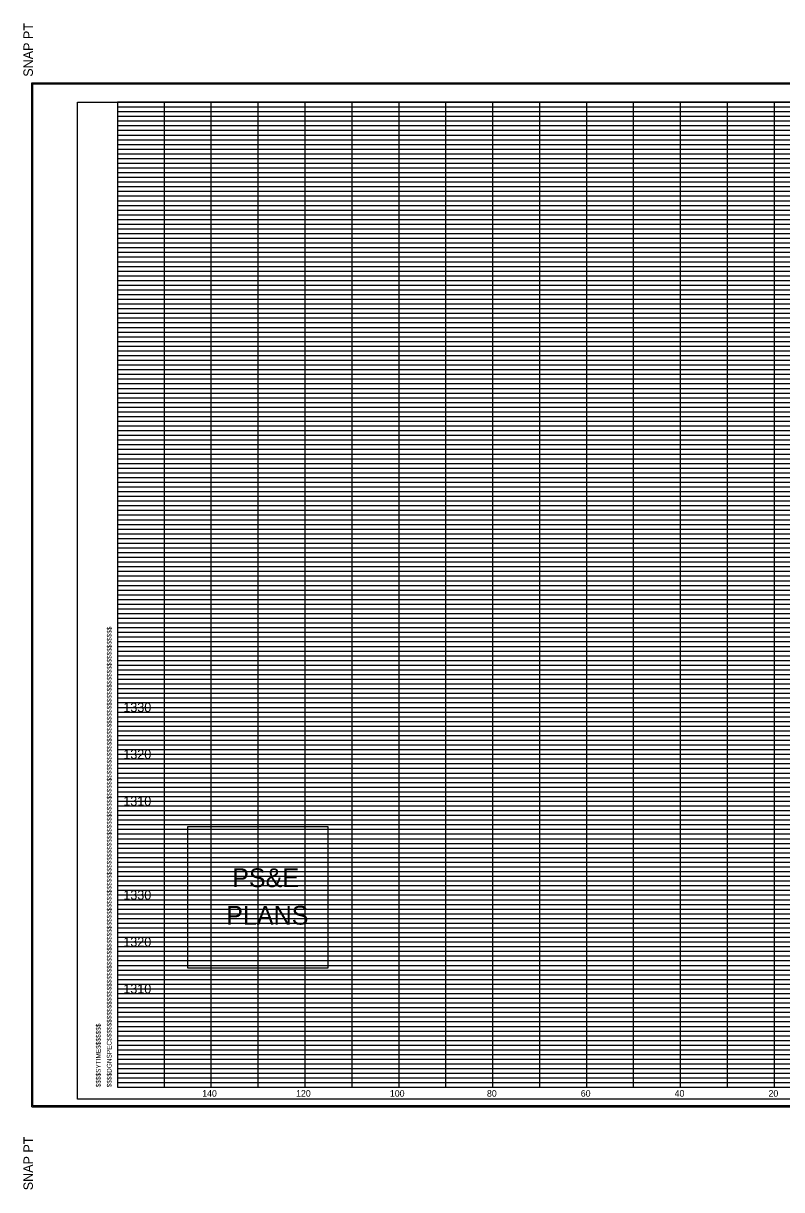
# Model space of a CAD drawing. Extents: x 980 to 1324, y 978 to 1227.
# Drawn here: x 979.9 to 1141.5, y 978.2 to 1226.8 of the extents above; entities that cross this region are included whole.
import ezdxf

# ---------------------------------------------------------------- set-up
doc = ezdxf.new("R2010")
doc.units = 0
for name, color, linetype in [('DESIGN - SHEET - Corner Text', 7, 'Continuous'), ('DESIGN - SHEET - Light Grid', 7, 'Continuous'), ('DESIGN - SHEET - Linework', 7, 'Continuous'), ('DESIGN - SHEET - Plot Shape', 7, 'Continuous'), ('DESIGN - TYPICAL - Finished Grade and Subgrade', 7, 'Continuous')]:
    doc.layers.add(name, color=color, linetype=linetype)

# ---------------------------------------------------------------- blocks, each defined once
blk = doc.blocks.new('XSTSHT')
at = {"layer": 'DESIGN - SHEET - Light Grid'}
for p, q in [((0, 20.9), (8, 20.9)), ((8, 20.9), (16, 20.9)), ((0, 20.8), (8, 20.8)), ((0, 20.7), (8, 20.7)), ((8, 20.8), (16, 20.8)), ((8, 20.7), (16, 20.7)), ((0, 20.6), (8, 20.6)), ((0, 20.5), (8, 20.5)), ((0, 20.4), (8, 20.4)), ((8, 20.6), (16, 20.6)), ((8, 20.5), (16, 20.5)), ((8, 20.4), (16, 20.4)), ((0, 20.3), (8, 20.3)), ((0, 20.2), (8, 20.2)), ((8, 20.3), (16, 20.3)), ((8, 20.2), (16, 20.2)), ((0, 20.1), (8, 20.1)), ((0, 19.9), (8, 19.9)), ((8, 20.1), (16, 20.1)), ((8, 19.9), (16, 19.9)), ((0, 19.8), (8, 19.8)), ((0, 19.7), (8, 19.7)), ((8, 19.8), (16, 19.8)), ((8, 19.7), (16, 19.7)), ((0, 19.6), (8, 19.6)), ((0, 19.5), (8, 19.5)), ((0, 19.4), (8, 19.4)), ((8, 19.6), (16, 19.6)), ((8, 19.5), (16, 19.5)), ((8, 19.4), (16, 19.4)), ((0, 19.3), (8, 19.3)), ((0, 19.2), (8, 19.2)), ((8, 19.3), (16, 19.3)), ((8, 19.2), (16, 19.2)), ((0, 19.1), (8, 19.1)), ((0, 18.9), (8, 18.9)), ((8, 19.1), (16, 19.1)), ((8, 18.9), (16, 18.9)), ((0, 18.8), (8, 18.8)), ((0, 18.7), (8, 18.7)), ((8, 18.8), (16, 18.8)), ((8, 18.7), (16, 18.7)), ((0, 18.6), (8, 18.6)), ((0, 18.5), (8, 18.5)), ((0, 18.4), (8, 18.4)), ((8, 18.6), (16, 18.6)), ((8, 18.5), (16, 18.5)), ((8, 18.4), (16, 18.4)), ((0, 18.3), (8, 18.3)), ((0, 18.2), (8, 18.2)), ((8, 18.3), (16, 18.3)), ((8, 18.2), (16, 18.2)), ((0, 18.1), (8, 18.1)), ((8, 18.1), (16, 18.1)), ((0, 17.9), (8, 17.9)), ((0, 17.8), (8, 17.8)), ((0, 17.7), (8, 17.7)), ((8, 17.9), (16, 17.9)), ((8, 17.8), (16, 17.8)), ((8, 17.7), (16, 17.7)), ((0, 17.6), (8, 17.6)), ((0, 17.5), (8, 17.5)), ((8, 17.6), (16, 17.6)), ((8, 17.5), (16, 17.5)), ((0, 17.4), (8, 17.4)), ((0, 17.3), (8, 17.3)), ((0, 17.2), (8, 17.2)), ((8, 17.4), (16, 17.4)), ((8, 17.3), (16, 17.3)), ((8, 17.2), (16, 17.2)), ((0, 17.1), (8, 17.1)), ((8, 17.1), (16, 17.1)), ((0, 16.9), (8, 16.9)), ((0, 16.8), (8, 16.8)), ((0, 16.7), (8, 16.7)), ((8, 16.9), (16, 16.9)), ((8, 16.8), (16, 16.8)), ((8, 16.7), (16, 16.7)), ((0, 16.6), (8, 16.6)), ((0, 16.5), (8, 16.5)), ((8, 16.6), (16, 16.6)), ((8, 16.5), (16, 16.5)), ((0, 16.4), (8, 16.4)), ((0, 16.3), (8, 16.3)), ((0, 16.2), (8, 16.2)), ((8, 16.4), (16, 16.4)), ((8, 16.3), (16, 16.3)), ((8, 16.2), (16, 16.2)), ((0, 16.1), (8, 16.1)), ((8, 16.1), (16, 16.1)), ((0, 15.9), (8, 15.9)), ((0, 15.8), (8, 15.8)), ((0, 15.7), (8, 15.7)), ((8, 15.9), (16, 15.9)), ((8, 15.8), (16, 15.8)), ((8, 15.7), (16, 15.7)), ((0, 15.6), (8, 15.6)), ((0, 15.5), (8, 15.5)), ((8, 15.6), (16, 15.6)), ((8, 15.5), (16, 15.5)), ((0, 15.4), (8, 15.4)), ((0, 15.3), (8, 15.3)), ((0, 15.2), (8, 15.2)), ((8, 15.4), (16, 15.4)), ((8, 15.3), (16, 15.3)), ((8, 15.2), (16, 15.2)), ((0, 15.1), (8, 15.1)), ((8, 15.1), (16, 15.1)), ((0, 14.9), (8, 14.9)), ((0, 14.8), (8, 14.8)), ((0, 14.7), (8, 14.7)), ((8, 14.9), (16, 14.9)), ((8, 14.8), (16, 14.8)), ((8, 14.7), (16, 14.7)), ((0, 14.6), (8, 14.6)), ((0, 14.5), (8, 14.5)), ((8, 14.6), (16, 14.6)), ((8, 14.5), (16, 14.5)), ((0, 14.4), (8, 14.4)), ((0, 14.3), (8, 14.3)), ((0, 14.2), (8, 14.2)), ((8, 14.4), (16, 14.4)), ((8, 14.3), (16, 14.3)), ((8, 14.2), (16, 14.2)), ((0, 14.1), (8, 14.1)), ((8, 14.1), (16, 14.1)), ((0, 13.9), (8, 13.9)), ((0, 13.8), (8, 13.8)), ((0, 13.7), (8, 13.7)), ((8, 13.9), (16, 13.9)), ((8, 13.8), (16, 13.8)), ((8, 13.7), (16, 13.7)), ((0, 13.6), (8, 13.6)), ((0, 13.5), (8, 13.5)), ((8, 13.6), (16, 13.6)), ((8, 13.5), (16, 13.5)), ((0, 13.4), (8, 13.4)), ((0, 13.3), (8, 13.3)), ((0, 13.2), (8, 13.2)), ((8, 13.4), (16, 13.4)), ((8, 13.3), (16, 13.3)), ((8, 13.2), (16, 13.2)), ((0, 13.1), (8, 13.1)), ((8, 13.1), (16, 13.1)), ((0, 12.9), (8, 12.9)), ((0, 12.8), (8, 12.8)), ((0, 12.7), (8, 12.7)), ((8, 12.9), (16, 12.9)), ((8, 12.8), (16, 12.8)), ((8, 12.7), (16, 12.7)), ((0, 12.6), (8, 12.6)), ((0, 12.5), (8, 12.5)), ((8, 12.6), (16, 12.6)), ((8, 12.5), (16, 12.5)), ((0, 12.4), (8, 12.4)), ((0, 12.3), (8, 12.3)), ((0, 12.2), (8, 12.2)), ((8, 12.4), (16, 12.4)), ((8, 12.3), (16, 12.3)), ((8, 12.2), (16, 12.2)), ((0, 12.1), (8, 12.1)), ((8, 12.1), (16, 12.1)), ((0, 11.9), (8, 11.9)), ((0, 11.8), (8, 11.8)), ((0, 11.7), (8, 11.7)), ((8, 11.9), (16, 11.9)), ((8, 11.8), (16, 11.8)), ((8, 11.7), (16, 11.7)), ((0, 11.6), (8, 11.6)), ((0, 11.5), (8, 11.5)), ((8, 11.6), (16, 11.6)), ((8, 11.5), (16, 11.5)), ((0, 11.4), (8, 11.4)), ((0, 11.3), (8, 11.3)), ((0, 11.2), (8, 11.2)), ((8, 11.4), (16, 11.4)), ((8, 11.3), (16, 11.3)), ((8, 11.2), (16, 11.2)), ((0, 11.1), (8, 11.1)), ((8, 11.1), (16, 11.1)), ((0, 10.9), (8, 10.9)), ((0, 10.8), (8, 10.8)), ((0, 10.7), (8, 10.7)), ((8, 10.9), (16, 10.9)), ((8, 10.8), (16, 10.8)), ((8, 10.7), (16, 10.7)), ((0, 10.6), (8, 10.6)), ((0, 10.5), (8, 10.5)), ((8, 10.6), (16, 10.6)), ((8, 10.5), (16, 10.5)), ((0, 10.4), (8, 10.4)), ((0, 10.3), (8, 10.3)), ((0, 10.2), (8, 10.2)), ((8, 10.4), (16, 10.4)), ((8, 10.3), (16, 10.3)), ((8, 10.2), (16, 10.2)), ((0, 10.1), (8, 10.1)), ((8, 10.1), (16, 10.1)), ((0, 9.9), (8, 9.9)), ((0, 9.8), (8, 9.8)), ((0, 9.7), (8, 9.7)), ((8, 9.9), (16, 9.9)), ((8, 9.8), (16, 9.8)), ((8, 9.7), (16, 9.7)), ((0, 9.6), (8, 9.6)), ((0, 9.5), (8, 9.5)), ((8, 9.6), (16, 9.6)), ((8, 9.5), (16, 9.5)), ((0, 9.4), (8, 9.4)), ((0, 9.3), (8, 9.3)), ((0, 9.2), (8, 9.2)), ((8, 9.4), (16, 9.4)), ((8, 9.3), (16, 9.3)), ((8, 9.2), (16, 9.2)), ((0, 9.1), (8, 9.1)), ((8, 9.1), (16, 9.1)), ((0, 8.9), (8, 8.9)), ((0, 8.8), (8, 8.8)), ((8, 8.9), (16, 8.9)), ((8, 8.8), (16, 8.8)), ((0, 8.7), (8, 8.7)), ((0, 8.6), (8, 8.6)), ((0, 8.5), (8, 8.5)), ((8, 8.7), (16, 8.7)), ((8, 8.6), (16, 8.6)), ((8, 8.5), (16, 8.5)), ((0, 8.4), (8, 8.4)), ((0, 8.3), (8, 8.3)), ((8, 8.4), (16, 8.4)), ((8, 8.3), (16, 8.3)), ((0, 8.2), (8, 8.2)), ((0, 8.1), (8, 8.1)), ((8, 8.2), (16, 8.2)), ((8, 8.1), (16, 8.1)), ((0, 7.9), (8, 7.9)), ((0, 7.8), (8, 7.8)), ((8, 7.9), (16, 7.9)), ((8, 7.8), (16, 7.8)), ((0, 7.7), (8, 7.7)), ((0, 7.6), (8, 7.6)), ((0, 7.5), (8, 7.5)), ((8, 7.7), (16, 7.7)), ((8, 7.6), (16, 7.6)), ((8, 7.5), (16, 7.5)), ((0, 7.4), (8, 7.4)), ((0, 7.3), (8, 7.3)), ((8, 7.4), (16, 7.4)), ((8, 7.3), (16, 7.3)), ((0, 7.2), (8, 7.2)), ((0, 7.1), (8, 7.1)), ((8, 7.2), (16, 7.2)), ((8, 7.1), (16, 7.1)), ((0, 6.9), (8, 6.9)), ((0, 6.8), (8, 6.8)), ((8, 6.9), (16, 6.9)), ((8, 6.8), (16, 6.8)), ((0, 6.7), (8, 6.7)), ((0, 6.6), (8, 6.6)), ((0, 6.5), (8, 6.5)), ((8, 6.7), (16, 6.7)), ((8, 6.6), (16, 6.6)), ((8, 6.5), (16, 6.5)), ((0, 6.4), (8, 6.4)), ((0, 6.3), (8, 6.3)), ((8, 6.4), (16, 6.4)), ((8, 6.3), (16, 6.3)), ((0, 6.2), (8, 6.2)), ((0, 6.1), (8, 6.1)), ((8, 6.2), (16, 6.2)), ((8, 6.1), (16, 6.1)), ((0, 5.9), (8, 5.9)), ((0, 5.8), (8, 5.8)), ((8, 5.9), (16, 5.9)), ((8, 5.8), (16, 5.8)), ((0, 5.7), (8, 5.7)), ((0, 5.6), (8, 5.6)), ((0, 5.5), (8, 5.5)), ((8, 5.7), (16, 5.7)), ((8, 5.6), (16, 5.6)), ((8, 5.5), (16, 5.5)), ((0, 5.4), (8, 5.4)), ((0, 5.3), (8, 5.3)), ((8, 5.4), (16, 5.4)), ((8, 5.3), (16, 5.3)), ((0, 5.2), (8, 5.2)), ((0, 5.1), (8, 5.1)), ((8, 5.2), (16, 5.2)), ((8, 5.1), (16, 5.1)), ((0, 4.9), (8, 4.9)), ((0, 4.8), (8, 4.8)), ((8, 4.9), (16, 4.9)), ((8, 4.8), (16, 4.8)), ((0, 4.7), (8, 4.7)), ((0, 4.6), (8, 4.6)), ((0, 4.5), (8, 4.5)), ((8, 4.7), (16, 4.7)), ((8, 4.6), (16, 4.6)), ((8, 4.5), (16, 4.5)), ((0, 4.4), (8, 4.4)), ((0, 4.3), (8, 4.3)), ((8, 4.4), (16, 4.4)), ((8, 4.3), (16, 4.3)), ((0, 4.2), (8, 4.2)), ((0, 4.1), (8, 4.1)), ((8, 4.2), (16, 4.2)), ((8, 4.1), (16, 4.1)), ((0, 3.9), (8, 3.9)), ((0, 3.8), (8, 3.8)), ((8, 3.9), (16, 3.9)), ((8, 3.8), (16, 3.8)), ((0, 3.7), (8, 3.7)), ((0, 3.6), (8, 3.6)), ((0, 3.5), (8, 3.5)), ((8, 3.7), (16, 3.7)), ((8, 3.6), (16, 3.6)), ((8, 3.5), (16, 3.5)), ((0, 3.4), (8, 3.4)), ((0, 3.3), (8, 3.3)), ((8, 3.4), (16, 3.4)), ((8, 3.3), (16, 3.3)), ((0, 3.2), (8, 3.2)), ((0, 3.1), (8, 3.1)), ((8, 3.2), (16, 3.2)), ((8, 3.1), (16, 3.1)), ((0, 2.9), (8, 2.9)), ((0, 2.8), (8, 2.8)), ((8, 2.9), (16, 2.9)), ((8, 2.8), (16, 2.8)), ((0, 2.7), (8, 2.7)), ((0, 2.6), (8, 2.6)), ((0, 2.5), (8, 2.5)), ((8, 2.7), (16, 2.7)), ((8, 2.6), (16, 2.6)), ((8, 2.5), (16, 2.5)), ((0, 2.4), (8, 2.4)), ((0, 2.3), (8, 2.3)), ((8, 2.4), (16, 2.4)), ((8, 2.3), (16, 2.3)), ((0, 2.2), (8, 2.2)), ((0, 2.1), (8, 2.1)), ((8, 2.2), (16, 2.2)), ((8, 2.1), (16, 2.1)), ((0, 1.9), (8, 1.9)), ((0, 1.8), (8, 1.8)), ((8, 1.9), (16, 1.9)), ((8, 1.8), (16, 1.8)), ((0, 1.7), (8, 1.7)), ((0, 1.6), (8, 1.6)), ((0, 1.5), (8, 1.5)), ((8, 1.7), (16, 1.7)), ((8, 1.6), (16, 1.6)), ((8, 1.5), (16, 1.5)), ((0, 1.4), (8, 1.4)), ((0, 1.3), (8, 1.3)), ((8, 1.4), (16, 1.4)), ((8, 1.3), (16, 1.3)), ((0, 1.2), (8, 1.2)), ((0, 1.1), (8, 1.1)), ((8, 1.2), (16, 1.2)), ((8, 1.1), (16, 1.1)), ((0, 0.9), (8, 0.9)), ((0, 0.8), (8, 0.8)), ((8, 0.9), (16, 0.9)), ((8, 0.8), (16, 0.8)), ((0, 0.7), (8, 0.7)), ((0, 0.6), (8, 0.6)), ((0, 0.5), (8, 0.5)), ((8, 0.7), (16, 0.7)), ((8, 0.6), (16, 0.6)), ((8, 0.5), (16, 0.5)), ((0, 0.4), (8, 0.4)), ((0, 0.3), (8, 0.3)), ((8, 0.4), (16, 0.4)), ((8, 0.3), (16, 0.3)), ((0, 0.2), (8, 0.2)), ((0, 0.1), (8, 0.1)), ((8, 0.2), (16, 0.2)), ((8, 0.1), (16, 0.1))]:
    blk.add_line(p, q, dxfattribs=at)
at = {"layer": 'DESIGN - SHEET - Linework'}
for p, q in [((-1.823, -0.414), (-1.823, 21.414)), ((-1.823, 21.414), (32.217, 21.414)), ((1, 0), (1, 21)), ((2, 0), (2, 21)), ((3, 0), (3, 21)), ((4, 0), (4, 21)), ((5, 0), (5, 21)), ((6, 0), (6, 21)), ((7, 0), (7, 21)), ((8, 0), (8, 21)), ((9, 0), (9, 21)), ((10, 0), (10, 21)), ((11, 0), (11, 21)), ((12, 0), (12, 21)), ((13, 0), (13, 21)), ((14, 0), (14, 21)), ((0, 20), (28, 20)), ((0, 19), (32, 19)), ((0, 18), (32, 18)), ((0, 17), (32, 17)), ((0, 16), (32, 16)), ((0, 15), (32, 15)), ((0, 14), (32, 14)), ((0, 13), (32, 13)), ((0, 12), (32, 12)), ((0, 11), (32, 11)), ((0, 10), (32, 10)), ((0, 9), (32, 9)), ((0, 8), (32, 8)), ((0, 7), (32, 7)), ((0, 6), (32, 6)), ((0, 5), (32, 5)), ((0, 4), (32, 4)), ((0, 3), (32, 3)), ((0, 2), (32, 2)), ((0, 1), (32, 1)), ((-1.823, -0.414), (32.217, -0.414))]:
    blk.add_line(p, q, dxfattribs=at)
blk.add_lwpolyline([(0, 21), (0, 0), (32, 0), (32, 21), (0, 21)], dxfattribs=at)
at = {"layer": 'DESIGN - SHEET - Plot Shape'}
for points in [[(-1.803, 21.394), (32.197, 21.394), (32.197, -0.394), (-1.803, -0.394)], [(-0.85, 21), (32, 21), (32, -0.25), (-0.85, -0.25)]]:
    blk.add_lwpolyline(points, close=True, dxfattribs=at)
at = {"layer": 'DESIGN - SHEET - Corner Text'}
for s, height, p in [('  SNAP PT', 0.2, (-1.803, 21.394)), ('$$$$DGNSPEC$$$$$$$$$$$$$$$$$$$$$$$$$$$$$$$$$$$$$$$$$$$$$$$$$$$$$$$$$$$$$$$$$$$$$$$$$$$$$$$$$$$$$$$$$$$$$$$$$$$$$$$$$$$$$$$$$$$', 0.100002, (-0.126, 0)), ('$$$$SYTIME$$$$$$$', 0.1, (-0.358, 0)), ('SNAP PT  ', 0.2, (-1.803, -2.194))]:
    blk.add_text(s, height=height, rotation=90, dxfattribs=at).set_placement(p)

msp = doc.modelspace()

# ---------------------------------------------------------------- linework, layer by layer
at = {"layer": 'DESIGN - SHEET - Corner Text'}
msp.add_lwpolyline([(1014.92, 1055.5), (1014.92, 1025.5), (1044.92, 1025.5), (1044.92, 1055.5)], close=True, dxfattribs=at)

# ---------------------------------------------------------------- block references
at = {"layer": 'DESIGN - TYPICAL - Finished Grade and Subgrade', "xscale": 10, "yscale": 10}
msp.add_blockref('XSTSHT', (1000, 1000), dxfattribs=at)

# ---------------------------------------------------------------- texts
at = {"layer": 'DESIGN - SHEET - Corner Text'}
for s, height, p in [('1330', 2, (1001.25, 1080)), ('1320', 2, (1001.25, 1070)), ('1310', 2, (1001.25, 1060)), ('PS&E', 4, (1024.44, 1042.68)), ('1330', 2, (1001.25, 1040)), ('PLANS', 4, (1023.16, 1034.68)), ('1320', 2, (1001.25, 1030)), ('1310', 2, (1001.25, 1020)), ('140', 1.4, (1018.06, 998)), ('120', 1.4, (1038.06, 998)), ('100', 1.4, (1058.06, 998)), ('80', 1.4, (1078.74, 998)), ('60', 1.4, (1098.74, 998)), ('40', 1.4, (1118.74, 998)), ('20', 1.4, (1138.74, 998))]:
    msp.add_text(s, height=height, dxfattribs=at).set_placement(p)

doc.saveas('drawing.dxf')
